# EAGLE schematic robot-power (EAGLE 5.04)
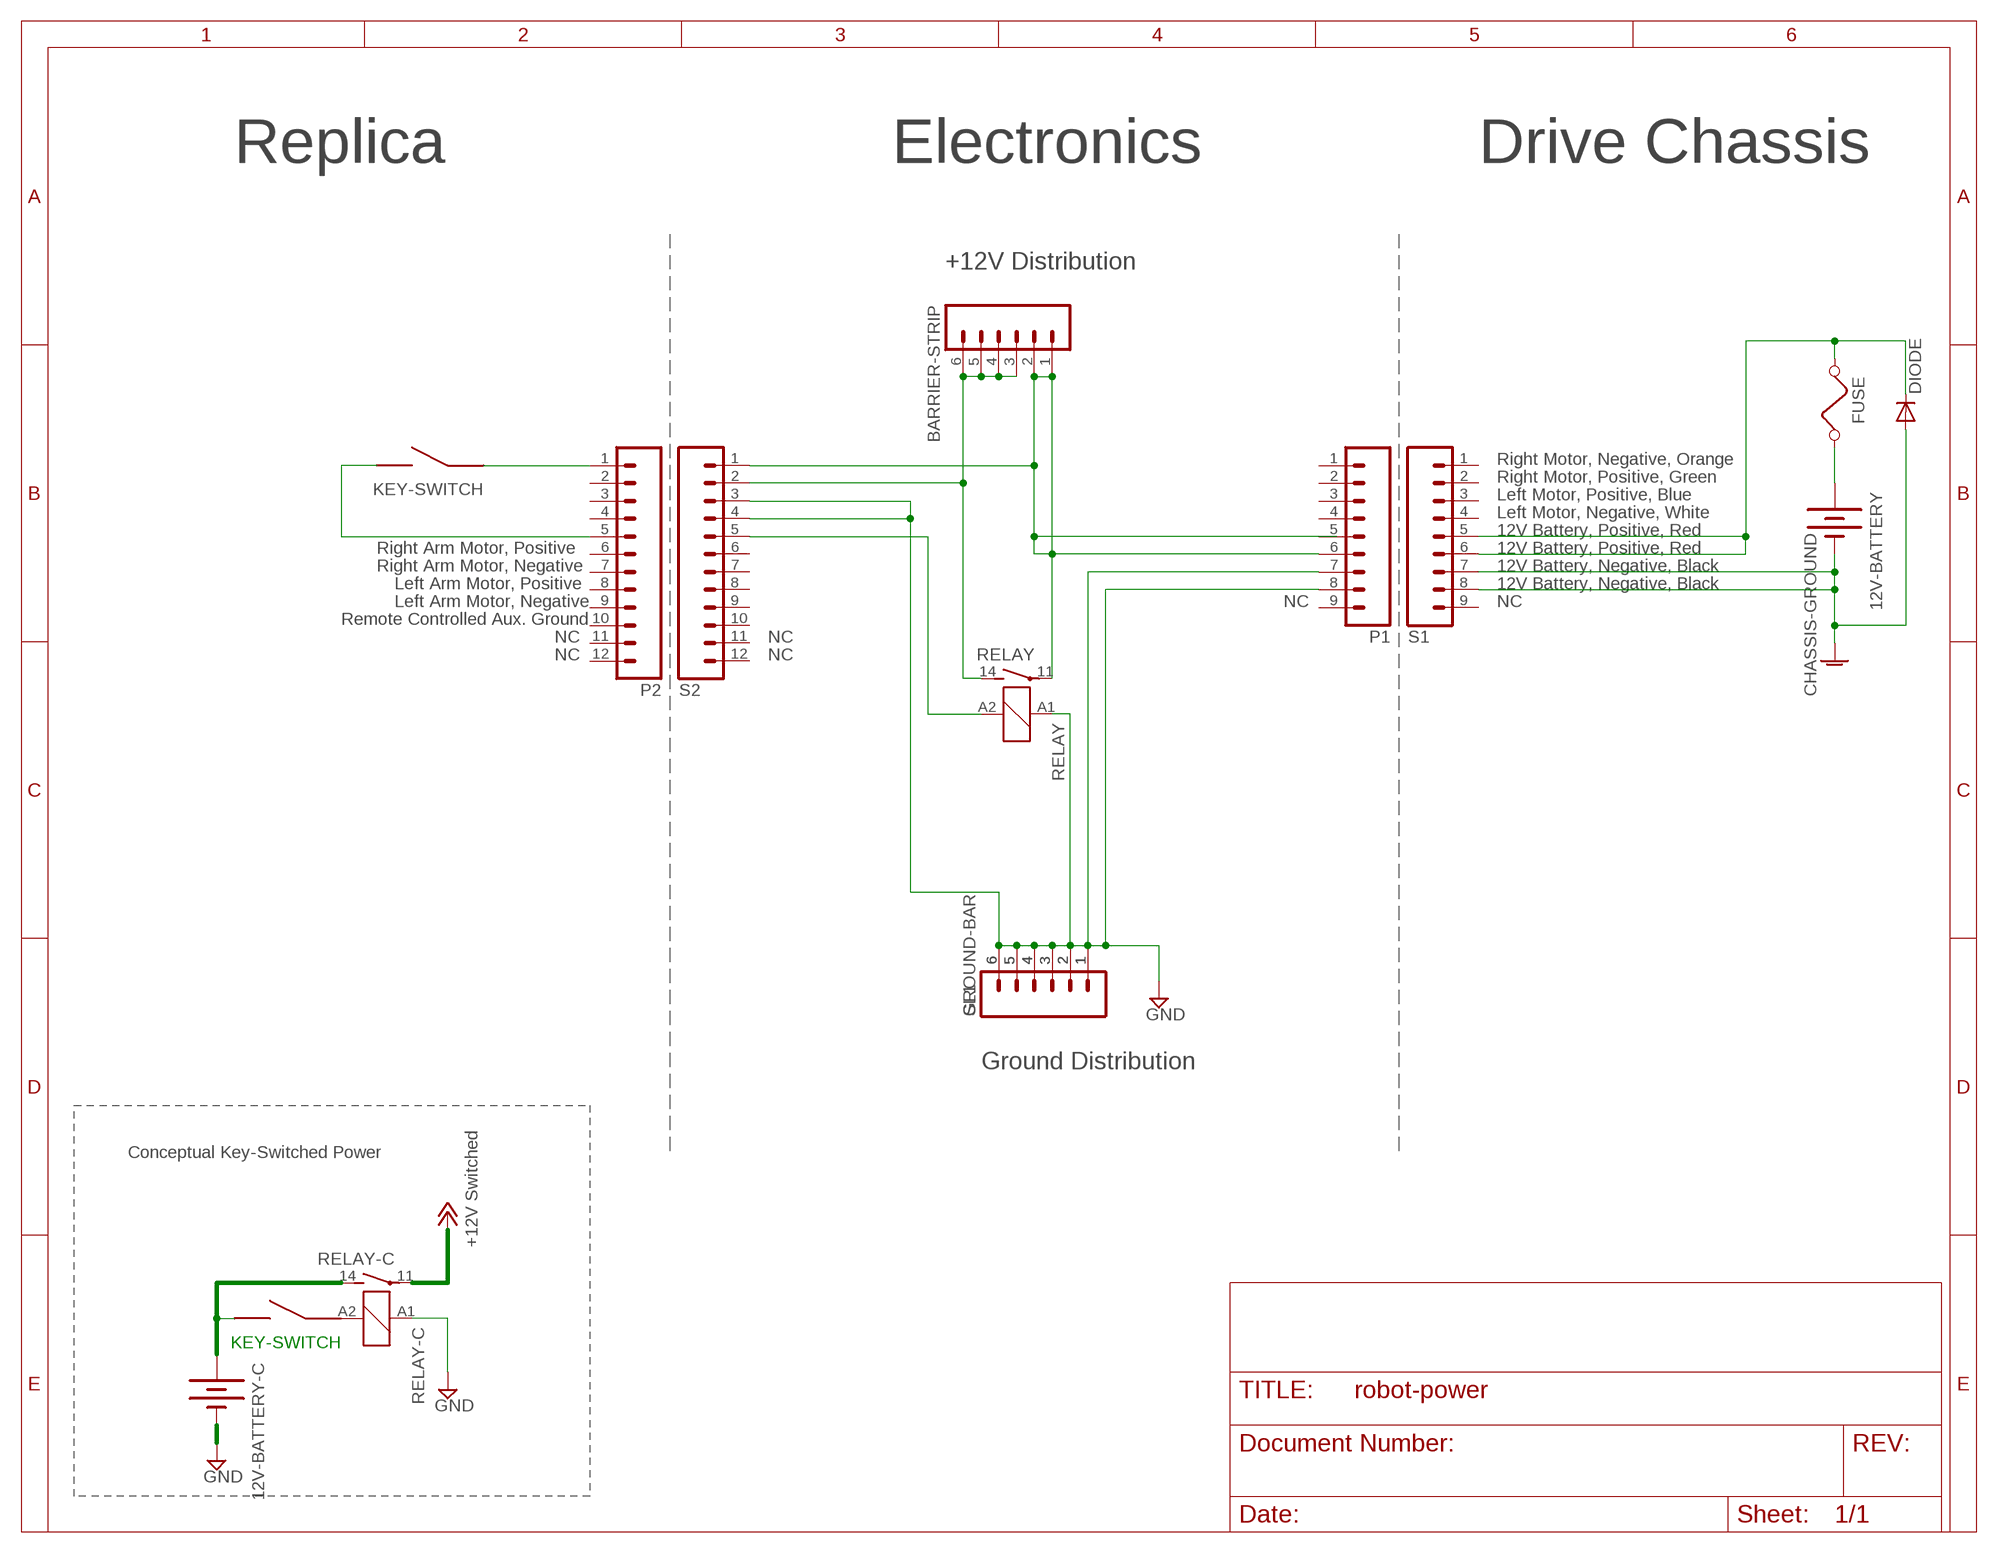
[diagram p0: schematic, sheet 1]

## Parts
12V-BATTERY  BATTERYAA  [BATTERY-AA]
12V-BATTERY-C  BATTERYAA  [BATTERY-AA]
BARRIER-STRIP  M06  [06P]
DIODE  BA296  [P2-15]
FUSE  FUSE  [FUSE]
GROUND-BAR  M06  [06P]
KEY-SWITCH  KEY-SWITCH  PUSH-BUTTON-SWITCH  [2SIL]
KEY-SWITCH1  KEY-SWITCH  PUSH-BUTTON-SWITCH  [2SIL]
P1  M09  [09P]
P2  M12  [12P]
RELAY  RT184005  [RT-N/O12A3.5]
RELAY-C  RT184005  [RT-N/O12A3.5]
S1  M09  [09P]
S2  M12  [12P]
SL1  M06  [06P]

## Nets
+12V: RELAY-C.11(2:P) ; supply symbol labelled +12V Switched
GND: 12V-BATTERY-C.GND@1(-) 12V-BATTERY.GND@1(-) DIODE.A GROUND-BAR.1 GROUND-BAR.2 GROUND-BAR.3 GROUND-BAR.4 GROUND-BAR.5 GROUND-BAR.6 P1.7 P1.8 RELAY-C.A1 RELAY.A1 S1.7 S1.8 S2.3 S2.4 SL1.1 SL1.2 SL1.3 SL1.4 SL1.5 SL1.6 ; supply symbol labelled CHASSIS-GROUND
N$1: KEY-SWITCH1.NO P2.1
N$2: KEY-SWITCH1.COM P2.5
N$3: RELAY.A2 S2.5
N$4: BARRIER-STRIP.3 BARRIER-STRIP.4 BARRIER-STRIP.5 BARRIER-STRIP.6 RELAY.14(2:S) S2.2
N$5: 12V-BATTERY.PWR@1(+) FUSE.2
N$6: DIODE.C FUSE.1 S1.5 S1.6
N$9: BARRIER-STRIP.1 BARRIER-STRIP.2 P1.6 RELAY.11(2:P) S2.1
N$29: KEY-SWITCH.NO RELAY-C.A2
N$30: 12V-BATTERY-C.PWR@1(+) KEY-SWITCH.COM RELAY-C.14(2:S)
Unconnected: P1.1 P1.2 P1.3 P1.4 P1.5 P1.9 P2.2 P2.3 P2.4 P2.6 P2.7 P2.8 P2.9 P2.10 P2.11 P2.12 S1.1 S1.2 S1.3 S1.4 S1.9 S2.6 S2.7 S2.8 S2.9 S2.10 S2.11 S2.12

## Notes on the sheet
- Replica | Electronics | Drive Chassis
- +12V Distribution
- Right Motor, Negative, Orange
- KEY-SWITCH | Right Motor, Positive, Green
- Left Motor, Positive, Blue
- Left Motor, Negative, White
- 12V Battery, Positive, Red
- Right Arm Motor, Positive | 12V Battery, Positive, Red
- Right Arm Motor, Negative | 12V Battery, Negative, Black
- Left Arm Motor, Positive | 12V Battery, Negative, Black
- Left Arm Motor, Negative | NC | NC
- Remote Controlled Aux. Ground
- NC | NC
- NC | NC
- Ground Distribution
- Conceptual Key-Switched Power
- KEY-SWITCH

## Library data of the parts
12V-BATTERY 12V-BATTERY-C = SparkFun:BATTERY: Battery Holders
BARRIER-STRIP GROUND-BAR SL1 = con-amp-quick:M06: AMP QUICK CONNECTOR
DIODE = diode:BA296: DIODE
FUSE = special:FUSE: FUSE
KEY-SWITCH KEY-SWITCH1 = trl:PUSH-BUTTON-SWITCH
P1 S1 = con-amp-quick:M09: AMP QUICK CONNECTOR
P2 S2 = con-amp-quick:M12: AMP QUICK CONNECTOR
RELAY RELAY-C = relay:RT?*: Power PCB Relay SCHRACK 1 pole 12 / 16 A, DC- or AC-coil Source: http://www.schrack.com/.. 5819.pdf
